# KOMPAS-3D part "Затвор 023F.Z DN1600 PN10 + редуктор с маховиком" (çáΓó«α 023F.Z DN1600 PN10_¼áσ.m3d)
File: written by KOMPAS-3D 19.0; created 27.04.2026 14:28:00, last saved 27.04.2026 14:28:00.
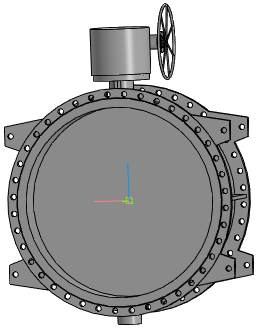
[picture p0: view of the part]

Document properties: Автор: Энергия; Полное имя файла: ..\..\Затвор 023F.Z DN200-DN1600_с маховиком\Затвор 023F.Z DN1600 PN10 + редуктор с маховиком.a3d

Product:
- Part/product: Затвор 023F.Z DN1600 PN10 + редуктор с маховиком
    Масса: 4224.06

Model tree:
1. Операция без истории:1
